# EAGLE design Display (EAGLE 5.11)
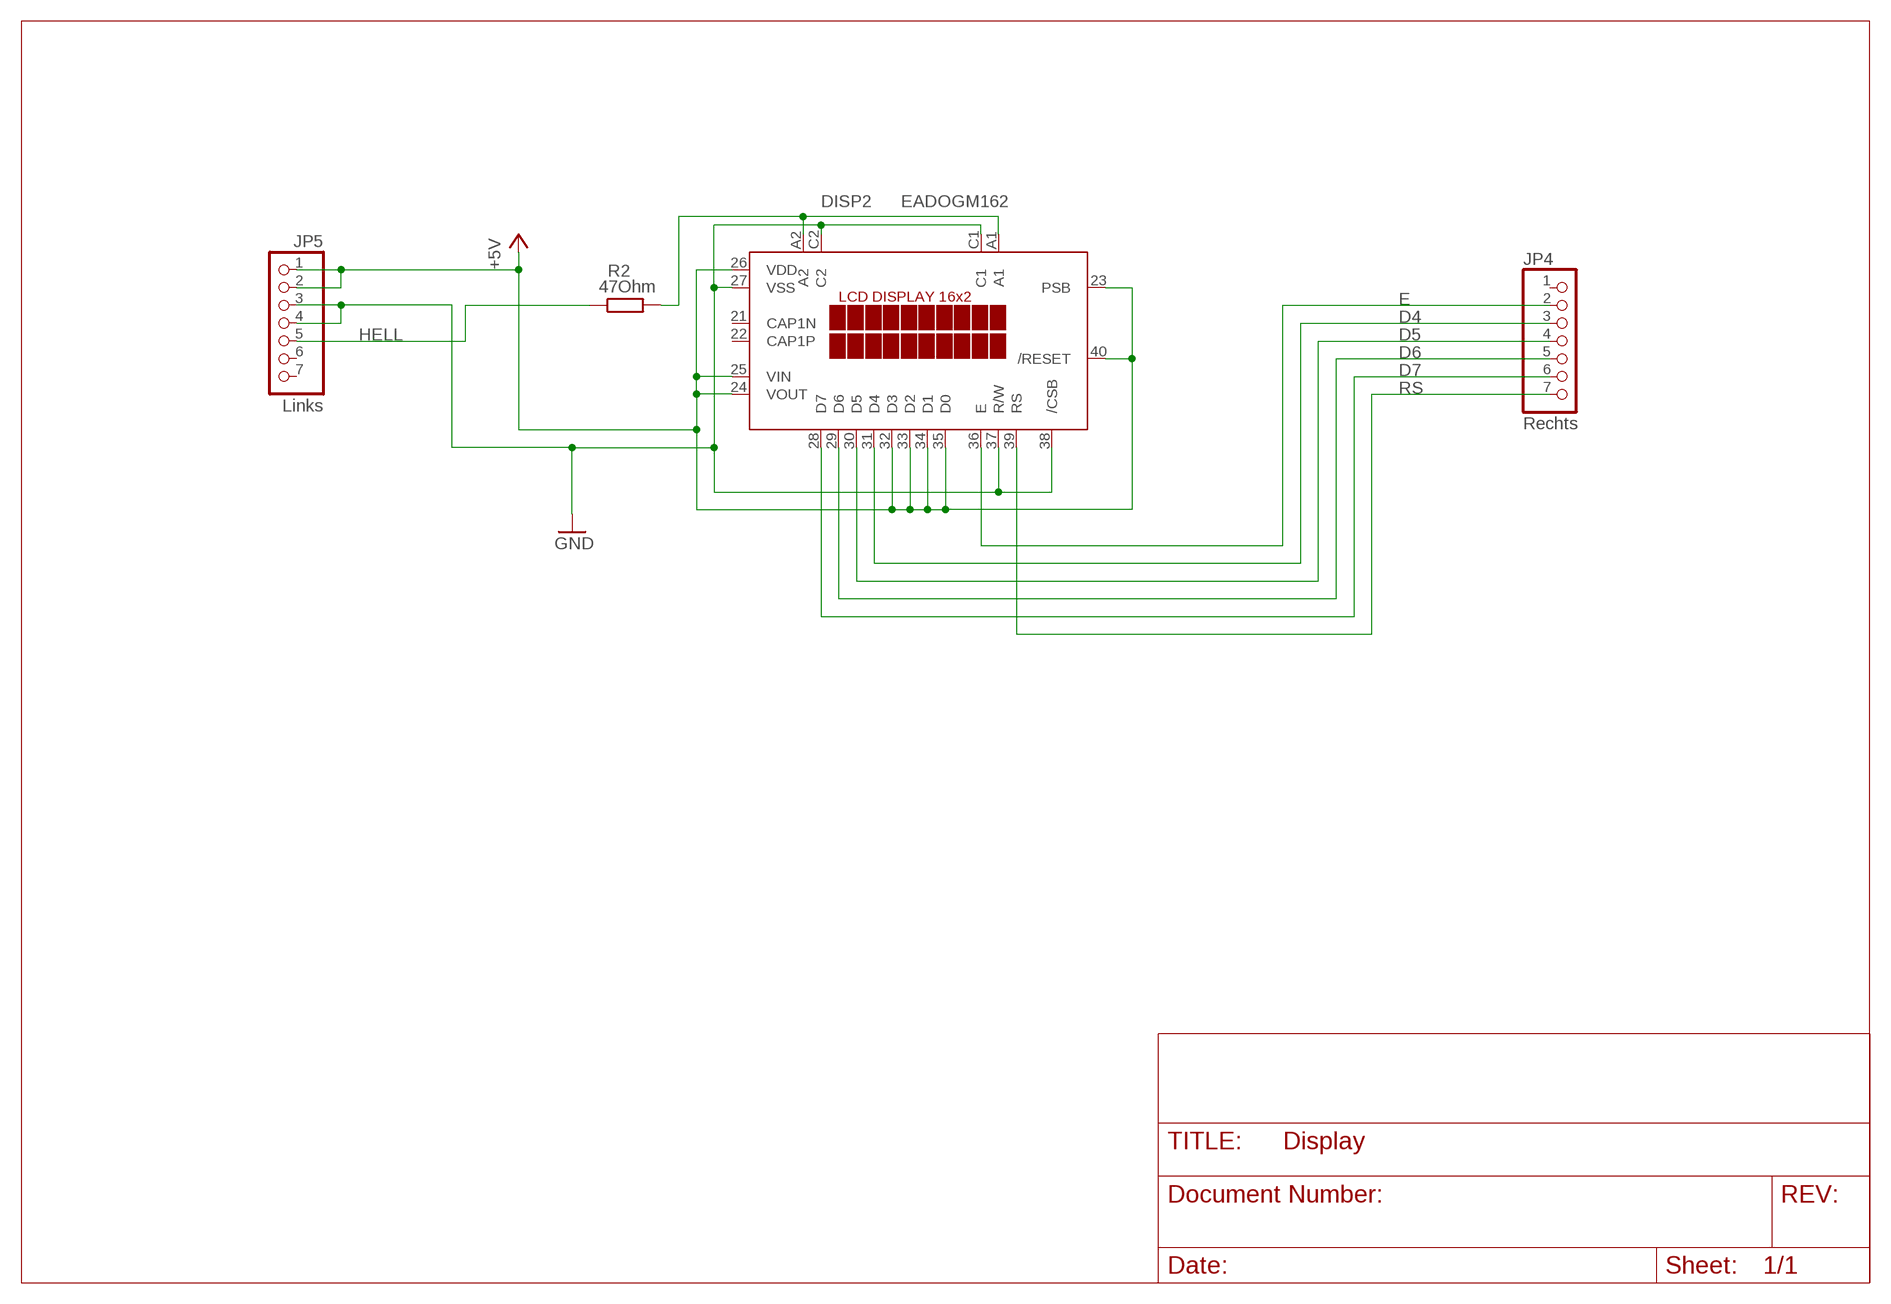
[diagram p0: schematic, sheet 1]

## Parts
DISP2  EADOGM162  [EADOGM162]
JP4  Rechts  PINHD-1X7  [1X07]
JP5  Links  PINHD-1X7  [1X07]
R2  47Ohm  WIDERSTAND_10  [207.10]

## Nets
+5V: DISP2.23(PSB) DISP2.24(VOUT) DISP2.25(VIN) DISP2.26(VDD) DISP2.32(D3) DISP2.33(D2) DISP2.34(D1) DISP2.35(D0) DISP2.40(/RESET) JP5.1 JP5.2
D4: DISP2.31(D4) JP4.3
D5: DISP2.30(D5) JP4.4
D6: DISP2.29(D6) JP4.5
D7: DISP2.28(D7) JP4.6
E: DISP2.36(E) JP4.2
GND: DISP2.27(VSS) DISP2.37(R/W) DISP2.38(/CSB) DISP2.C1 DISP2.C2 JP5.3 JP5.4
HELL: JP5.5 R2.1
N$5: DISP2.A1 DISP2.A2 R2.2
RS: DISP2.39(RS) JP4.7
Unconnected: DISP2.21(CAP1N) DISP2.22(CAP1P) JP4.1 JP5.6 JP5.7

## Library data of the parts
DISP2 = 1Eigene:EADOGM162
JP4 JP5 = pinhead:PINHD-1X7: PIN HEADER
R2 = Eigene:WIDERSTAND_10

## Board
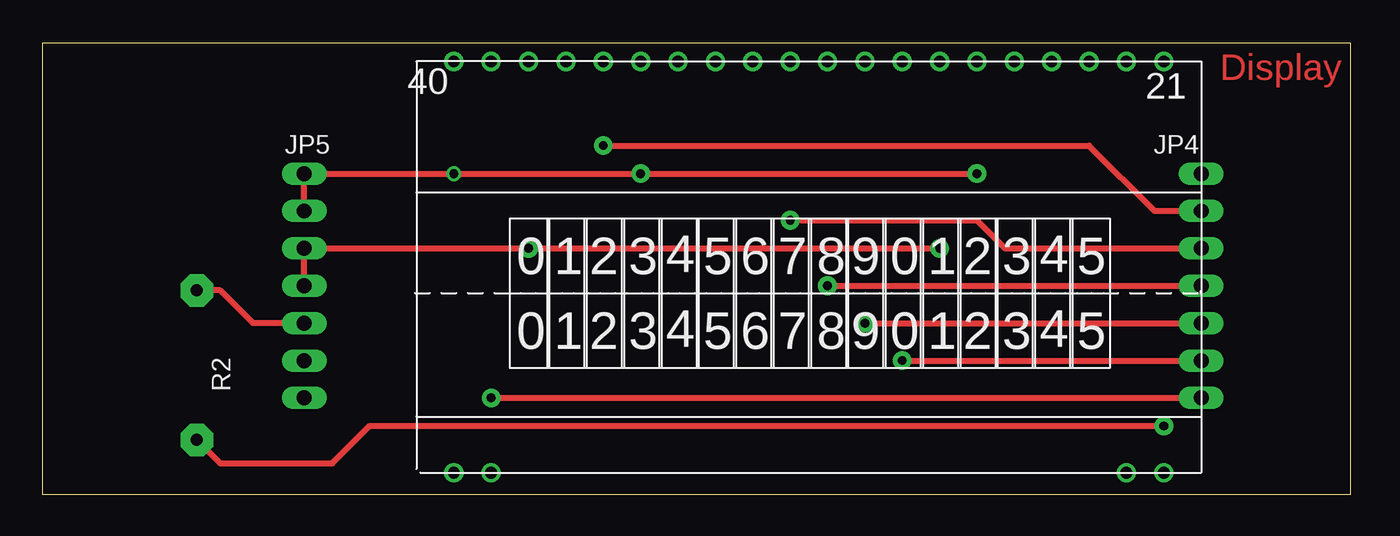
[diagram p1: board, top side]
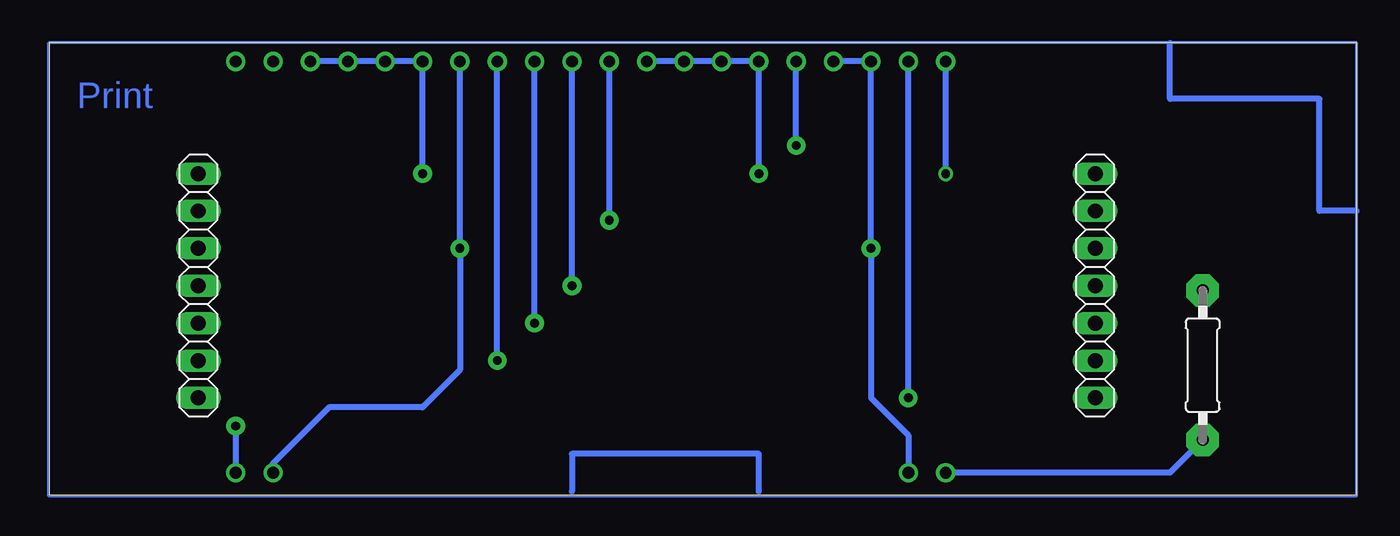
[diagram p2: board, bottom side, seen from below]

Size 88.88 x 30.71 mm. Coordinates in mm from the lower left corner, seen from the top.
Outline: 0,30.71 88.88,30.71 88.88,0 0,0 0,30.71
Copper layers (1*16): Top 0.035mm / dielectric 1.5mm / Bottom 0.035mm
Design rules "default *": minimum track width 0.4mm, minimum drill 0.6mm, track to track 0.4mm, track to pad 0.4mm, pad to pad 0.4mm, via to via 0.4mm, smd to smd 0.3mm, copper to edge 0mil, drill to drill 8mil, minimum pad ring 10mil, minimum via ring 8mil, stop-mask expansion 4mil, vias tented up to drill 0mil, thermal gap 10mil

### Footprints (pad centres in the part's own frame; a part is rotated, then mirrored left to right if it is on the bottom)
EADOGM162 = drill 0.8 pad 1.27 round: 21 25.4,15.24; 22 22.86,15.24; 23 20.32,15.24; 24 17.78,15.24; 25 15.24,15.24; 26 12.7,15.24; 27 10.16,15.24; 28 7.62,15.24; 29 5.08,15.24; 30 2.54,15.24; 31 0,15.24; 32 -2.54,15.24; 33 -5.08,15.24; 34 -7.62,15.24; 35 -10.16,15.24; 36 -12.7,15.24; 37 -15.24,15.24; 38 -17.78,15.24; 39 -20.32,15.24; 40 -22.86,15.24; A1 -22.86,-12.7; A2 25.4,-12.7; C1 -20.32,-12.7; C2 22.86,-12.7
1X07 = drill 1.016 long: 1 -7.62,0; 2 -5.08,0; 3 -2.54,0; 4 0,0; 5 2.54,0; 6 5.08,0; 7 7.62,0
207.10 = drill 0.813 pad 2.184 octagon: 1 -5.08,0; 2 5.08,0

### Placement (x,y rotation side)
DISP2  50.8,14.2 0 top
JP4  78.74,14.2 270 bottom
JP5  17.78,14.2 270 bottom
R2  10.48,8.8 270 bottom

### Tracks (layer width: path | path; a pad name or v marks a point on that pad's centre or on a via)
+5V  (via drill 0.6, 0.6 pad 1.27)
  Top 0.406: v63.5,21.82 v40.64,21.82 v27.94,21.82 JP5.1 JP5.2
  Bottom 0.406: DISP2.32 DISP2.33 DISP2.34 DISP2.35 v40.64,21.82 | v27.94,21.82 DISP2.40 | DISP2.23 DISP2.24 DISP2.25 DISP2.26 v63.5,21.82
D4  (via drill 0.6 pad 1.27)
  Top 0.406: JP4.3 65.41,16.74 63.5,18.64 v50.8,18.64
  Bottom 0.406: v50.8,18.64 DISP2.31
D5  (via drill 0.6 pad 1.27)
  Top 0.406: v53.34,14.2 JP4.4
  Bottom 0.406: v53.34,14.2 DISP2.30
D6  (via drill 0.6 pad 1.27)
  Top 0.406: v55.88,11.66 JP4.5
  Bottom 0.406: v55.88,11.66 DISP2.29
D7  (via drill 0.6 pad 1.27)
  Top 0.406: v58.42,9.12 JP4.6
  Bottom 0.406: v58.42,9.12 DISP2.28
E  (via drill 0.6 pad 1.27)
  Top 0.406: JP4.2 75.56,19.28 71.12,23.72 v38.1,23.72
  Bottom 0.406: v38.1,23.72 DISP2.36
GND  (via drill 0.6 pad 1.27)
  Top 0.406: JP5.4 JP5.3 v33.02,16.74 v60.96,16.74
  Bottom 0.406: DISP2.37 DISP2.38 v33.02,16.74 33.02,6.58 30.48,4.04 DISP2.C1 | DISP2.27 v60.96,16.74 60.96,8.48 63.5,5.94 69.85,5.94 73.66,2.13 DISP2.C2
HELL
  Top 0.406: JP5.5 14.29,11.66 12.06,13.88 R2.1
N$1
  Bottom 0.406: 0,19.28 2.54,19.28 2.54,26.9 12.7,26.9 12.7,30.71
N$2
  Bottom 0.406: 40.64,0.23 40.64,2.77 53.34,2.77 53.34,0.23
N$3
  Bottom 0.2: 0,30.71 88.9,30.71 88.9,-0.09 0,-0.09 0,30.71
N$5  (via drill 0.6 pad 1.27)
  Top 0.406: R2.2 12.06,2.13 19.69,2.13 22.23,4.67 v76.2,4.67
  Bottom 0.406: DISP2.A1 12.7,1.5 R2.2 | v76.2,4.67 DISP2.A2
RS  (via drill 0.6 pad 1.27)
  Top 0.406: v30.48,6.58 JP4.7
  Bottom 0.406: v30.48,6.58 DISP2.39

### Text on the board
Top: Display
Bottom: Print
tNames: 40 | 21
